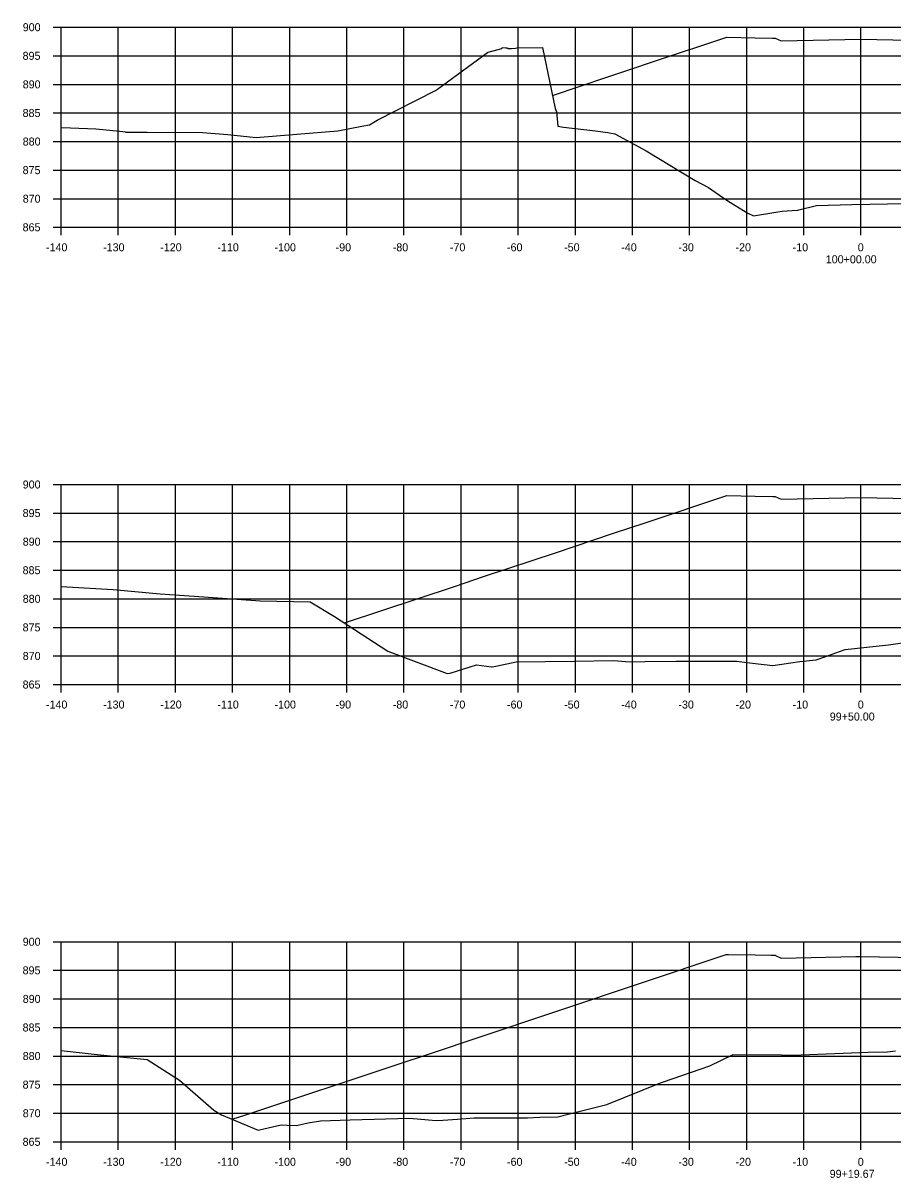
# Model space of a CAD drawing. Extents: x 1098669 to 1198896, y 698679 to 704410.
# Drawn here: x 1113352.2 to 1113504.5, y 702232.2 to 702434.3 of the extents above; entities that cross this region are included whole.
import ezdxf

# ---------------------------------------------------------------- set-up
doc = ezdxf.new("R2010")
doc.units = 0
for name, color, linetype in [('R_Alt Surface', 7, 'Continuous'), ('R_Axis', 7, 'Continuous'), ('R_Axis Annot', 7, 'Continuous'), ('R_Fin Surface', 7, 'Continuous'), ('R_Grid', 7, 'Continuous')]:
    doc.layers.add(name, color=color, linetype=linetype)

msp = doc.modelspace()

# ---------------------------------------------------------------- linework, layer by layer
at = {"layer": 'R_Alt Surface'}
for points in [[(1113358.87, 702415.99), (1113360.49, 702415.96), (1113364.91, 702415.77), (1113369.15, 702415.36), (1113369.66, 702415.34), (1113370.13, 702415.27), (1113370.15, 702415.23), (1113373.93, 702415.2), (1113383.59, 702415.17), (1113388.04, 702414.77), (1113393, 702414.29), (1113400.14, 702414.87), (1113407.32, 702415.46), (1113411.48, 702416.26), (1113412.82, 702416.51), (1113414.19, 702417.29), (1113424.42, 702422.48), (1113424.76, 702422.7), (1113433.49, 702429.15), (1113433.51, 702429.15), (1113433.64, 702429.19), (1113435.99, 702429.85), (1113436.07, 702430.02), (1113436.68, 702429.94), (1113437, 702429.94), (1113437.06, 702429.84), (1113437.71, 702429.85), (1113438.41, 702429.92), (1113438.61, 702429.93), (1113443.11, 702430.02), (1113445.33, 702419.37), (1113445.58, 702418.76), (1113445.82, 702416.27), (1113446.81, 702416.08), (1113452.38, 702415.43), (1113454.57, 702415.14), (1113455.8, 702414.92), (1113461.28, 702411.92), (1113469.84, 702406.77), (1113472.19, 702405.52), (1113474.69, 702403.79), (1113476.02, 702402.89), (1113479.06, 702401.01), (1113480.03, 702400.59), (1113483.95, 702401.19), (1113485.09, 702401.38), (1113486.8, 702401.5), (1113487.8, 702401.58), (1113487.97, 702401.62), (1113491.07, 702402.4), (1113497.26, 702402.53), (1113506.69, 702402.73)], [(1113358.87, 702335.73), (1113367.96, 702335.16), (1113376.17, 702334.42), (1113383.83, 702333.9), (1113393.69, 702333.23), (1113402.43, 702333.04), (1113406.71, 702330.45), (1113416.02, 702324.42), (1113426.42, 702320.52), (1113426.96, 702320.56), (1113431.54, 702322.02), (1113434.18, 702321.67), (1113434.29, 702321.66), (1113434.98, 702321.8), (1113438.51, 702322.53), (1113448.69, 702322.64), (1113455.62, 702322.77), (1113457.63, 702322.62), (1113458.45, 702322.56), (1113461.02, 702322.61), (1113466.48, 702322.64), (1113474.96, 702322.66), (1113477.07, 702322.65), (1113479.86, 702322.32), (1113483.45, 702321.87), (1113488.14, 702322.59), (1113491.03, 702322.89), (1113492.56, 702323.43), (1113495.13, 702324.34), (1113496.11, 702324.68), (1113503.69, 702325.53), (1113511.32, 702326.6)], [(1113358.87, 702254.51), (1113365.15, 702253.86), (1113373.91, 702252.96), (1113379.6, 702249.32), (1113385.6, 702244.08), (1113386.96, 702243.25), (1113393.33, 702240.59), (1113393.61, 702240.65), (1113397.37, 702241.51), (1113398.44, 702241.48), (1113400.05, 702241.41), (1113402.09, 702241.85), (1113404.28, 702242.25), (1113409.44, 702242.4), (1113413.63, 702242.51), (1113419.83, 702242.67), (1113423.14, 702242.39), (1113424.5, 702242.28), (1113425.68, 702242.34), (1113428.22, 702242.53), (1113431.18, 702242.76), (1113435.7, 702242.77), (1113440.52, 702242.78), (1113442.64, 702242.87), (1113445.81, 702242.93), (1113448.1, 702243.53), (1113454.36, 702245.09), (1113463.78, 702248.89), (1113464.31, 702249.07), (1113472.39, 702251.85), (1113476.52, 702253.81), (1113484.98, 702253.76), (1113486.97, 702253.72), (1113500.13, 702254.25), (1113503.54, 702254.29), (1113504.92, 702254.48)]]:
    msp.add_lwpolyline(points, dxfattribs=at)
at = {"layer": 'R_Axis'}
for p, q in [((1113357.47, 702433.56), (1113358.87, 702433.56)), ((1113358.87, 702398.56), (1113358.87, 702433.56)), ((1113357.47, 702428.56), (1113358.87, 702428.56)), ((1113357.47, 702423.56), (1113358.87, 702423.56)), ((1113357.47, 702418.56), (1113358.87, 702418.56)), ((1113357.47, 702413.56), (1113358.87, 702413.56)), ((1113357.47, 702408.56), (1113358.87, 702408.56)), ((1113357.47, 702403.56), (1113358.87, 702403.56)), ((1113357.47, 702398.56), (1113358.87, 702398.56)), ((1113358.87, 702398.56), (1113638.87, 702398.56)), ((1113358.87, 702397.16), (1113358.87, 702398.56)), ((1113368.87, 702397.16), (1113368.87, 702398.56)), ((1113378.87, 702397.16), (1113378.87, 702398.56)), ((1113388.87, 702397.16), (1113388.87, 702398.56)), ((1113398.87, 702397.16), (1113398.87, 702398.56)), ((1113408.87, 702397.16), (1113408.87, 702398.56)), ((1113418.87, 702397.16), (1113418.87, 702398.56)), ((1113428.87, 702397.16), (1113428.87, 702398.56)), ((1113438.87, 702397.16), (1113438.87, 702398.56)), ((1113448.87, 702397.16), (1113448.87, 702398.56)), ((1113458.87, 702397.16), (1113458.87, 702398.56)), ((1113468.87, 702397.16), (1113468.87, 702398.56)), ((1113478.87, 702397.16), (1113478.87, 702398.56)), ((1113488.87, 702397.16), (1113488.87, 702398.56)), ((1113498.87, 702397.16), (1113498.87, 702398.56)), ((1113357.47, 702353.56), (1113358.87, 702353.56)), ((1113358.87, 702318.56), (1113358.87, 702353.56)), ((1113357.47, 702348.56), (1113358.87, 702348.56)), ((1113357.47, 702343.56), (1113358.87, 702343.56)), ((1113357.47, 702338.56), (1113358.87, 702338.56)), ((1113357.47, 702333.56), (1113358.87, 702333.56)), ((1113357.47, 702328.56), (1113358.87, 702328.56)), ((1113357.47, 702323.56), (1113358.87, 702323.56)), ((1113357.47, 702318.56), (1113358.87, 702318.56)), ((1113358.87, 702318.56), (1113638.87, 702318.56)), ((1113358.87, 702317.16), (1113358.87, 702318.56)), ((1113368.87, 702317.16), (1113368.87, 702318.56)), ((1113378.87, 702317.16), (1113378.87, 702318.56)), ((1113388.87, 702317.16), (1113388.87, 702318.56)), ((1113398.87, 702317.16), (1113398.87, 702318.56)), ((1113408.87, 702317.16), (1113408.87, 702318.56)), ((1113418.87, 702317.16), (1113418.87, 702318.56)), ((1113428.87, 702317.16), (1113428.87, 702318.56)), ((1113438.87, 702317.16), (1113438.87, 702318.56)), ((1113448.87, 702317.16), (1113448.87, 702318.56)), ((1113458.87, 702317.16), (1113458.87, 702318.56)), ((1113468.87, 702317.16), (1113468.87, 702318.56)), ((1113478.87, 702317.16), (1113478.87, 702318.56)), ((1113488.87, 702317.16), (1113488.87, 702318.56)), ((1113498.87, 702317.16), (1113498.87, 702318.56)), ((1113357.47, 702273.56), (1113358.87, 702273.56)), ((1113358.87, 702238.56), (1113358.87, 702273.56)), ((1113357.47, 702268.56), (1113358.87, 702268.56)), ((1113357.47, 702263.56), (1113358.87, 702263.56)), ((1113357.47, 702258.56), (1113358.87, 702258.56)), ((1113357.47, 702253.56), (1113358.87, 702253.56)), ((1113357.47, 702248.56), (1113358.87, 702248.56)), ((1113357.47, 702243.56), (1113358.87, 702243.56)), ((1113357.47, 702238.56), (1113358.87, 702238.56)), ((1113358.87, 702238.56), (1113638.87, 702238.56)), ((1113358.87, 702237.16), (1113358.87, 702238.56)), ((1113368.87, 702237.16), (1113368.87, 702238.56)), ((1113378.87, 702237.16), (1113378.87, 702238.56)), ((1113388.87, 702237.16), (1113388.87, 702238.56)), ((1113398.87, 702237.16), (1113398.87, 702238.56)), ((1113408.87, 702237.16), (1113408.87, 702238.56)), ((1113418.87, 702237.16), (1113418.87, 702238.56)), ((1113428.87, 702237.16), (1113428.87, 702238.56)), ((1113438.87, 702237.16), (1113438.87, 702238.56)), ((1113448.87, 702237.16), (1113448.87, 702238.56)), ((1113458.87, 702237.16), (1113458.87, 702238.56)), ((1113468.87, 702237.16), (1113468.87, 702238.56)), ((1113478.87, 702237.16), (1113478.87, 702238.56)), ((1113488.87, 702237.16), (1113488.87, 702238.56)), ((1113498.87, 702237.16), (1113498.87, 702238.56))]:
    msp.add_line(p, q, dxfattribs=at)
at = {"layer": 'R_Fin Surface'}
for points in [[(1113444.85, 702421.64), (1113454.54, 702424.87), (1113458.59, 702426.22), (1113462.54, 702427.54), (1113475.37, 702431.81), (1113480.37, 702431.71), (1113483.37, 702431.65), (1113483.87, 702431.65), (1113484.87, 702431.17), (1113498.87, 702431.45), (1113512.87, 702431.17), (1113513.87, 702431.65), (1113514.37, 702431.65), (1113517.37, 702431.71), (1113522.37, 702431.81), (1113597.11, 702406.9)], [(1113408.45, 702329.33), (1113427.7, 702335.74), (1113432.99, 702337.5), (1113445.37, 702341.63), (1113455.37, 702344.96), (1113461.27, 702346.93), (1113475.37, 702351.63), (1113480.37, 702351.53), (1113483.37, 702351.47), (1113483.87, 702351.47), (1113484.87, 702350.99), (1113498.87, 702351.27), (1113512.87, 702350.99), (1113513.87, 702351.47), (1113514.37, 702351.47), (1113517.37, 702351.53), (1113522.37, 702351.63), (1113583.92, 702331.11)], [(1113388.78, 702242.49), (1113388.97, 702242.55), (1113391.04, 702243.24), (1113392.41, 702243.69), (1113393.12, 702243.92), (1113416.26, 702251.63), (1113424.72, 702254.44), (1113431.14, 702256.58), (1113475.25, 702271.31), (1113475.37, 702271.35), (1113475.7, 702271.35), (1113480.37, 702271.25), (1113483.17, 702271.2), (1113483.37, 702271.19), (1113483.4, 702271.19), (1113483.87, 702271.19), (1113483.93, 702271.16), (1113484.87, 702270.71), (1113497.94, 702270.97), (1113498.87, 702270.99), (1113511.94, 702270.73)]]:
    msp.add_lwpolyline(points, dxfattribs=at)
at = {"layer": 'R_Grid'}
for p, q in [((1113358.87, 702433.56), (1113638.87, 702433.56)), ((1113358.87, 702398.56), (1113358.87, 702433.56)), ((1113368.87, 702398.56), (1113368.87, 702433.56)), ((1113378.87, 702398.56), (1113378.87, 702433.56)), ((1113388.87, 702398.56), (1113388.87, 702433.56)), ((1113398.87, 702398.56), (1113398.87, 702433.56)), ((1113408.87, 702398.56), (1113408.87, 702433.56)), ((1113418.87, 702398.56), (1113418.87, 702433.56)), ((1113428.87, 702398.56), (1113428.87, 702433.56)), ((1113438.87, 702398.56), (1113438.87, 702433.56)), ((1113448.87, 702398.56), (1113448.87, 702433.56)), ((1113458.87, 702398.56), (1113458.87, 702433.56)), ((1113468.87, 702398.56), (1113468.87, 702433.56)), ((1113478.87, 702398.56), (1113478.87, 702433.56)), ((1113488.87, 702398.56), (1113488.87, 702433.56)), ((1113498.87, 702398.56), (1113498.87, 702433.56)), ((1113358.87, 702428.56), (1113638.87, 702428.56)), ((1113358.87, 702423.56), (1113638.87, 702423.56)), ((1113358.87, 702418.56), (1113638.87, 702418.56)), ((1113358.87, 702413.56), (1113638.87, 702413.56)), ((1113358.87, 702408.56), (1113638.87, 702408.56)), ((1113358.87, 702403.56), (1113638.87, 702403.56)), ((1113358.87, 702398.56), (1113638.87, 702398.56)), ((1113358.87, 702353.56), (1113638.87, 702353.56)), ((1113358.87, 702318.56), (1113358.87, 702353.56)), ((1113368.87, 702318.56), (1113368.87, 702353.56)), ((1113378.87, 702318.56), (1113378.87, 702353.56)), ((1113388.87, 702318.56), (1113388.87, 702353.56)), ((1113398.87, 702318.56), (1113398.87, 702353.56)), ((1113408.87, 702318.56), (1113408.87, 702353.56)), ((1113418.87, 702318.56), (1113418.87, 702353.56)), ((1113428.87, 702318.56), (1113428.87, 702353.56)), ((1113438.87, 702318.56), (1113438.87, 702353.56)), ((1113448.87, 702318.56), (1113448.87, 702353.56)), ((1113458.87, 702318.56), (1113458.87, 702353.56)), ((1113468.87, 702318.56), (1113468.87, 702353.56)), ((1113478.87, 702318.56), (1113478.87, 702353.56)), ((1113488.87, 702318.56), (1113488.87, 702353.56)), ((1113498.87, 702318.56), (1113498.87, 702353.56)), ((1113358.87, 702348.56), (1113638.87, 702348.56)), ((1113358.87, 702343.56), (1113638.87, 702343.56)), ((1113358.87, 702338.56), (1113638.87, 702338.56)), ((1113358.87, 702333.56), (1113638.87, 702333.56)), ((1113358.87, 702328.56), (1113638.87, 702328.56)), ((1113358.87, 702323.56), (1113638.87, 702323.56)), ((1113358.87, 702318.56), (1113638.87, 702318.56)), ((1113358.87, 702273.56), (1113638.87, 702273.56)), ((1113358.87, 702238.56), (1113358.87, 702273.56)), ((1113368.87, 702238.56), (1113368.87, 702273.56)), ((1113378.87, 702238.56), (1113378.87, 702273.56)), ((1113388.87, 702238.56), (1113388.87, 702273.56)), ((1113398.87, 702238.56), (1113398.87, 702273.56)), ((1113408.87, 702238.56), (1113408.87, 702273.56)), ((1113418.87, 702238.56), (1113418.87, 702273.56)), ((1113428.87, 702238.56), (1113428.87, 702273.56)), ((1113438.87, 702238.56), (1113438.87, 702273.56)), ((1113448.87, 702238.56), (1113448.87, 702273.56)), ((1113458.87, 702238.56), (1113458.87, 702273.56)), ((1113468.87, 702238.56), (1113468.87, 702273.56)), ((1113478.87, 702238.56), (1113478.87, 702273.56)), ((1113488.87, 702238.56), (1113488.87, 702273.56)), ((1113498.87, 702238.56), (1113498.87, 702273.56)), ((1113358.87, 702268.56), (1113638.87, 702268.56)), ((1113358.87, 702263.56), (1113638.87, 702263.56)), ((1113358.87, 702258.56), (1113638.87, 702258.56)), ((1113358.87, 702253.56), (1113638.87, 702253.56)), ((1113358.87, 702248.56), (1113638.87, 702248.56)), ((1113358.87, 702243.56), (1113638.87, 702243.56)), ((1113358.87, 702238.56), (1113638.87, 702238.56))]:
    msp.add_line(p, q, dxfattribs=at)

# ---------------------------------------------------------------- texts
at = {"layer": 'R_Axis Annot'}
for s, p in [('900', (1113352.14, 702432.86)), ('895', (1113352.12, 702427.86)), ('890', (1113352.14, 702422.86)), ('885', (1113352.12, 702417.86)), ('880', (1113352.14, 702412.86)), ('875', (1113352.12, 702407.86)), ('870', (1113352.14, 702402.86)), ('865', (1113352.12, 702397.86)), ('-140', (1113356.21, 702394.36)), ('-130', (1113366.21, 702394.36)), ('-120', (1113376.21, 702394.36)), ('-110', (1113386.21, 702394.36)), ('-100', (1113396.21, 702394.36)), ('-90', (1113406.91, 702394.36)), ('-80', (1113416.91, 702394.36)), ('-70', (1113426.91, 702394.36)), ('-60', (1113436.91, 702394.36)), ('-50', (1113446.91, 702394.36)), ('-40', (1113456.91, 702394.36)), ('-30', (1113466.91, 702394.36)), ('-20', (1113476.91, 702394.36)), ('-10', (1113486.91, 702394.36)), ('0', (1113498.31, 702394.36)), ('100+00.00', (1113492.71, 702392.26)), ('900', (1113352.14, 702352.86)), ('895', (1113352.12, 702347.86)), ('890', (1113352.14, 702342.86)), ('885', (1113352.12, 702337.86)), ('880', (1113352.14, 702332.86)), ('875', (1113352.12, 702327.86)), ('870', (1113352.14, 702322.86)), ('865', (1113352.12, 702317.86)), ('-140', (1113356.21, 702314.36)), ('-130', (1113366.21, 702314.36)), ('-120', (1113376.21, 702314.36)), ('-110', (1113386.21, 702314.36)), ('-100', (1113396.21, 702314.36)), ('-90', (1113406.91, 702314.36)), ('-80', (1113416.91, 702314.36)), ('-70', (1113426.91, 702314.36)), ('-60', (1113436.91, 702314.36)), ('-50', (1113446.91, 702314.36)), ('-40', (1113456.91, 702314.36)), ('-30', (1113466.91, 702314.36)), ('-20', (1113476.91, 702314.36)), ('-10', (1113486.91, 702314.36)), ('0', (1113498.31, 702314.36)), ('99+50.00', (1113493.41, 702312.26)), ('900', (1113352.14, 702272.86)), ('895', (1113352.12, 702267.86)), ('890', (1113352.14, 702262.86)), ('885', (1113352.12, 702257.86)), ('880', (1113352.14, 702252.86)), ('875', (1113352.12, 702247.86)), ('870', (1113352.14, 702242.86)), ('865', (1113352.12, 702237.86)), ('-140', (1113356.21, 702234.36)), ('-130', (1113366.21, 702234.36)), ('-120', (1113376.21, 702234.36)), ('-110', (1113386.21, 702234.36)), ('-100', (1113396.21, 702234.36)), ('-90', (1113406.91, 702234.36)), ('-80', (1113416.91, 702234.36)), ('-70', (1113426.91, 702234.36)), ('-60', (1113436.91, 702234.36)), ('-50', (1113446.91, 702234.36)), ('-40', (1113456.91, 702234.36)), ('-30', (1113466.91, 702234.36)), ('-20', (1113476.91, 702234.36)), ('-10', (1113486.91, 702234.36)), ('0', (1113498.31, 702234.36)), ('99+19.67', (1113493.39, 702232.26))]:
    msp.add_text(s, height=1.4, dxfattribs=at).set_placement(p)

doc.saveas('drawing.dxf')
